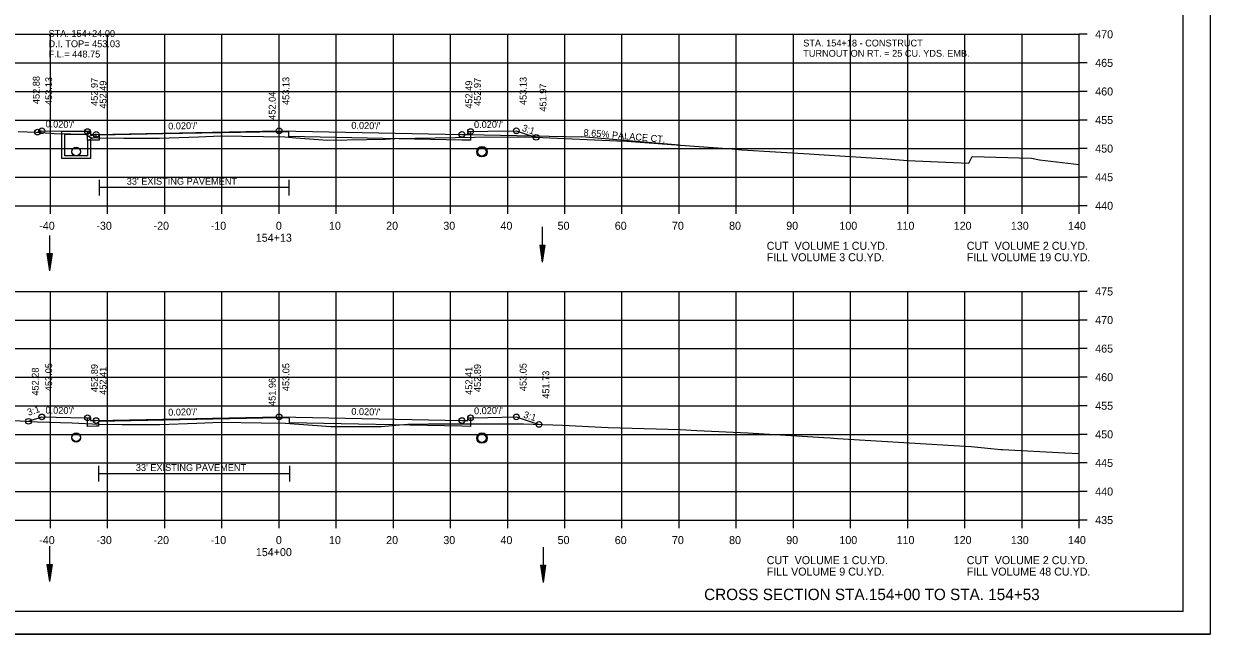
# Model space of a CAD drawing. Extents: x 1538688 to 1540766, y 656250 to 671912.
# Drawn here: x 1538813.5 to 1539021.1, y 665511.4 to 665618.3 of the extents above; entities that cross this region are included whole.
import ezdxf

# ---------------------------------------------------------------- set-up
doc = ezdxf.new("R2010")
doc.units = 0
for name, color, linetype in [('15', 7, 'Continuous'), ('16', 7, 'Continuous'), ('18', 7, 'Continuous'), ('20', 7, 'Continuous'), ('22', 7, 'Continuous'), ('26', 7, 'Continuous'), ('39', 7, 'Continuous'), ('40', 7, 'Continuous'), ('41', 7, 'Continuous'), ('42', 7, 'Continuous'), ('7', 7, 'Continuous'), ('Borings', 7, 'Continuous'), ('Horizontal Alignment', 7, 'Continuous'), ('RipRap', 7, 'Continuous'), ('Wall Heights', 7, 'Continuous')]:
    doc.layers.add(name, color=color, linetype=linetype)

msp = doc.modelspace()

# ---------------------------------------------------------------- linework, layer by layer
at = {"layer": '15'}
for p, q in [((1538817.56, 665578.04), (1538818.01, 665575.04)), ((1538817.56, 665578.04), (1538818.46, 665578.04)), ((1538817.64, 665578.04), (1538818.01, 665575.54)), ((1538817.71, 665578.04), (1538818.01, 665576.06)), ((1538817.79, 665578.04), (1538818.01, 665576.56)), ((1538817.87, 665578.04), (1538818.01, 665577.07)), ((1538817.94, 665578.04), (1538818.01, 665577.57)), ((1538818.46, 665578.04), (1538818.01, 665575.04)), ((1538818.16, 665578.04), (1538818.01, 665577.07)), ((1538818.31, 665578.04), (1538818.01, 665576.06)), ((1538818.39, 665578.04), (1538818.01, 665575.54)), ((1538818.23, 665578.04), (1538818.01, 665576.56)), ((1538818.08, 665578.04), (1538818.01, 665577.57)), ((1538903.79, 665579.51), (1538904.24, 665576.51)), ((1538903.79, 665579.51), (1538904.69, 665579.51)), ((1538903.86, 665579.51), (1538904.24, 665577.01)), ((1538903.94, 665579.51), (1538904.24, 665577.53)), ((1538904.02, 665579.51), (1538904.24, 665578.03)), ((1538904.09, 665579.51), (1538904.24, 665578.54)), ((1538904.17, 665579.51), (1538904.24, 665579.04)), ((1538904.69, 665579.51), (1538904.24, 665576.51)), ((1538904.39, 665579.51), (1538904.24, 665578.54)), ((1538904.54, 665579.51), (1538904.24, 665577.53)), ((1538904.61, 665579.51), (1538904.24, 665577.01)), ((1538904.46, 665579.51), (1538904.24, 665578.03)), ((1538904.31, 665579.51), (1538904.24, 665579.04)), ((1538817.56, 665523.65), (1538818.01, 665520.65)), ((1538817.56, 665523.65), (1538818.46, 665523.65)), ((1538817.64, 665523.65), (1538818.01, 665521.15)), ((1538817.71, 665523.65), (1538818.01, 665521.67)), ((1538817.79, 665523.65), (1538818.01, 665522.16)), ((1538817.87, 665523.65), (1538818.01, 665522.67)), ((1538817.94, 665523.65), (1538818.01, 665523.17)), ((1538818.46, 665523.65), (1538818.01, 665520.65)), ((1538818.16, 665523.65), (1538818.01, 665522.67)), ((1538818.31, 665523.65), (1538818.01, 665521.67)), ((1538818.39, 665523.65), (1538818.01, 665521.15)), ((1538818.23, 665523.65), (1538818.01, 665522.16)), ((1538818.08, 665523.65), (1538818.01, 665523.17)), ((1538903.92, 665523.5), (1538904.37, 665520.5)), ((1538903.92, 665523.5), (1538904.82, 665523.5)), ((1538904, 665523.5), (1538904.37, 665521)), ((1538904.07, 665523.5), (1538904.37, 665521.52)), ((1538904.15, 665523.5), (1538904.37, 665522.02)), ((1538904.23, 665523.5), (1538904.37, 665522.52)), ((1538904.3, 665523.5), (1538904.37, 665523.03)), ((1538904.82, 665523.5), (1538904.37, 665520.5)), ((1538904.52, 665523.5), (1538904.37, 665522.52)), ((1538904.67, 665523.5), (1538904.37, 665521.52)), ((1538904.75, 665523.5), (1538904.37, 665521)), ((1538904.6, 665523.5), (1538904.37, 665522.02)), ((1538904.44, 665523.5), (1538904.37, 665523.03))]:
    msp.add_line(p, q, dxfattribs=at)
at = {"layer": '16'}
for p in [(1538891.18, 665598.88), (1538928.17, 665597.01)]:
    msp.add_line(p, (1538911.17, 665598.48), dxfattribs=at)
at = {"layer": '18'}
for points in [[(1538812.51, 665599.4), (1538815.69, 665599.31), (1538818.82, 665599.07), (1538821.76, 665599.01), (1538824.37, 665598.95), (1538825.01, 665598.44), (1538825.07, 665598.39), (1538825.24, 665598.38), (1538826.59, 665598.27), (1538831.03, 665598.25), (1538837.25, 665598.23), (1538844.07, 665598.47), (1538847.97, 665598.62), (1538851.71, 665598.56), (1538859.17, 665598.44), (1538861.12, 665598.29), (1538866.67, 665597.87), (1538873.45, 665598.03), (1538876.66, 665598.05), (1538878.42, 665598.16), (1538889.06, 665598.37), (1538892.38, 665598.39), (1538901.31, 665598.44), (1538904.28, 665598.35), (1538917.29, 665597.77), (1538919.02, 665597.71), (1538928.42, 665596.99), (1538937.38, 665596.34), (1538939.14, 665596.22), (1538950.91, 665595.48), (1538953.54, 665595.29), (1538964.56, 665594.6), (1538968.14, 665594.35), (1538978.89, 665593.88), (1538979.47, 665595.05), (1538989.81, 665594.75), (1538991.24, 665594.44), (1538998.18, 665593.65)], [(1538811.87, 665548.81), (1538815.9, 665548.61), (1538821.98, 665548.43), (1538826.7, 665548.18), (1538830.74, 665548.16), (1538837.29, 665548.14), (1538843.79, 665548.38), (1538848.02, 665548.53), (1538855.07, 665548.42), (1538859.22, 665548.36), (1538866.45, 665547.82), (1538867.21, 665547.78), (1538868.76, 665547.78), (1538876.05, 665547.81), (1538879.26, 665548.09), (1538880.72, 665548.22), (1538884.33, 665548.24), (1538900.92, 665548.24), (1538907.77, 665548), (1538915.74, 665547.61), (1538928.37, 665547.24), (1538931.29, 665547.11), (1538940.21, 665546.66), (1538953.5, 665545.85), (1538954.63, 665545.78), (1538955.87, 665545.7), (1538976.25, 665544.44), (1538979.29, 665544.31), (1538984.49, 665543.78), (1538984.73, 665543.77), (1538995.69, 665543.19), (1538998.18, 665543.05)]]:
    msp.add_lwpolyline(points, dxfattribs=at)
at = {"layer": '20'}
for points in [[(1538815.92, 665599.29), (1538816.67, 665599.54), (1538821.67, 665599.44), (1538824.67, 665599.38), (1538825.17, 665599.38), (1538825.18, 665598.88), (1538826.18, 665598.9), (1538858.18, 665599.54), (1538890.18, 665598.9), (1538891.18, 665598.88), (1538891.19, 665599.38), (1538891.69, 665599.38), (1538894.69, 665599.44), (1538899.69, 665599.54), (1538903.16, 665598.38)], [(1538814.33, 665548.69), (1538816.67, 665549.47), (1538821.67, 665549.37), (1538824.67, 665549.31), (1538825.17, 665549.31), (1538825.18, 665548.81), (1538826.18, 665548.83), (1538858.18, 665549.47), (1538890.18, 665548.83), (1538891.18, 665548.81), (1538891.19, 665549.31), (1538891.69, 665549.31), (1538894.69, 665549.37), (1538899.69, 665549.47), (1538903.66, 665548.14)]]:
    msp.add_lwpolyline(points, dxfattribs=at)
at = {"layer": '22'}
for p, q in [((1538718.18, 665616.41), (1538998.18, 665616.41)), ((1538818.18, 665586.41), (1538818.18, 665616.41)), ((1538828.18, 665586.41), (1538828.18, 665616.41)), ((1538838.18, 665586.41), (1538838.18, 665616.41)), ((1538848.18, 665586.41), (1538848.18, 665616.41)), ((1538858.18, 665586.41), (1538858.18, 665616.41)), ((1538868.18, 665586.41), (1538868.18, 665616.41)), ((1538878.18, 665586.41), (1538878.18, 665616.41)), ((1538888.18, 665586.41), (1538888.18, 665616.41)), ((1538898.18, 665586.41), (1538898.18, 665616.41)), ((1538908.18, 665586.41), (1538908.18, 665616.41)), ((1538918.18, 665586.41), (1538918.18, 665616.41)), ((1538928.18, 665586.41), (1538928.18, 665616.41)), ((1538938.18, 665586.41), (1538938.18, 665616.41)), ((1538948.18, 665586.41), (1538948.18, 665616.41)), ((1538958.18, 665586.41), (1538958.18, 665616.41)), ((1538968.18, 665586.41), (1538968.18, 665616.41)), ((1538978.18, 665586.41), (1538978.18, 665616.41)), ((1538988.18, 665586.41), (1538988.18, 665616.41)), ((1538998.18, 665586.41), (1538998.18, 665616.41)), ((1538718.18, 665611.41), (1538998.18, 665611.41)), ((1538718.18, 665606.41), (1538998.18, 665606.41)), ((1538718.18, 665601.41), (1538998.18, 665601.41)), ((1538718.18, 665596.41), (1538998.18, 665596.41)), ((1538718.18, 665591.41), (1538998.18, 665591.41)), ((1538718.18, 665586.41), (1538998.18, 665586.41)), ((1538718.18, 665571.41), (1538998.18, 665571.41)), ((1538818.18, 665531.41), (1538818.18, 665571.41)), ((1538828.18, 665531.41), (1538828.18, 665571.41)), ((1538838.18, 665531.41), (1538838.18, 665571.41)), ((1538848.18, 665531.41), (1538848.18, 665571.41)), ((1538858.18, 665531.41), (1538858.18, 665571.41)), ((1538868.18, 665531.41), (1538868.18, 665571.41)), ((1538878.18, 665531.41), (1538878.18, 665571.41)), ((1538888.18, 665531.41), (1538888.18, 665571.41)), ((1538898.18, 665531.41), (1538898.18, 665571.41)), ((1538908.18, 665531.41), (1538908.18, 665571.41)), ((1538918.18, 665531.41), (1538918.18, 665571.41)), ((1538928.18, 665531.41), (1538928.18, 665571.41)), ((1538938.18, 665531.41), (1538938.18, 665571.41)), ((1538948.18, 665531.41), (1538948.18, 665571.41)), ((1538958.18, 665531.41), (1538958.18, 665571.41)), ((1538968.18, 665531.41), (1538968.18, 665571.41)), ((1538978.18, 665531.41), (1538978.18, 665571.41)), ((1538988.18, 665531.41), (1538988.18, 665571.41)), ((1538998.18, 665531.41), (1538998.18, 665571.41)), ((1538718.18, 665566.41), (1538998.18, 665566.41)), ((1538718.18, 665561.41), (1538998.18, 665561.41)), ((1538718.18, 665556.41), (1538998.18, 665556.41)), ((1538718.18, 665551.41), (1538998.18, 665551.41)), ((1538718.18, 665546.41), (1538998.18, 665546.41)), ((1538718.18, 665541.41), (1538998.18, 665541.41)), ((1538718.18, 665536.41), (1538998.18, 665536.41)), ((1538718.18, 665531.41), (1538998.18, 665531.41))]:
    msp.add_line(p, q, dxfattribs=at)
at = {"layer": '26'}
msp.add_line((1538687.78, 665511.44), (1539021.11, 665511.44), dxfattribs=at)
msp.add_lwpolyline([(1538687.77, 665724.77), (1539021.11, 665724.77), (1539021.11, 665511.43), (1538687.77, 665511.43)], close=True, dxfattribs=at)
for centre, radius in [((1538815.92, 665599.29), 0.5), ((1538816.67, 665599.54), 0.5), ((1538824.67, 665599.38), 0.5), ((1538826.18, 665598.9), 0.5), ((1538858.18, 665599.54), 0.5), ((1538890.18, 665598.9), 0.5), ((1538891.69, 665599.38), 0.5), ((1538899.69, 665599.54), 0.5), ((1538903.16, 665598.38), 0.5), ((1538893.68, 665595.86), 0.917), ((1538814.33, 665548.69), 0.5), ((1538816.67, 665549.47), 0.5), ((1538824.67, 665549.31), 0.5), ((1538826.18, 665548.83), 0.5), ((1538858.18, 665549.47), 0.5), ((1538890.18, 665548.83), 0.5), ((1538891.69, 665549.31), 0.5), ((1538899.69, 665549.47), 0.5), ((1538903.66, 665548.14), 0.5), ((1538893.68, 665545.76), 0.917)]:
    msp.add_circle(centre, radius, dxfattribs=at)
at = {"layer": '39'}
for p, q in [((1538820.18, 665599.44), (1538824.93, 665599.44)), ((1538820.18, 665597.94), (1538820.18, 665599.44)), ((1538820.68, 665597.94), (1538820.68, 665598.94)), ((1538820.68, 665598.94), (1538824.68, 665598.94)), ((1538825.01, 665599.28), (1538824.68, 665598.94)), ((1538826.18, 665598.96), (1538824.68, 665598.44)), ((1538824.68, 665597.94), (1538824.68, 665598.44)), ((1538825.01, 665599.28), (1538824.93, 665599.44)), ((1538826.18, 665598.43), (1538825.18, 665598.09)), ((1538825.18, 665597.94), (1538825.18, 665598.09)), ((1538904.24, 665582.7), (1538904.24, 665576.51)), ((1538818.01, 665581.23), (1538818.01, 665575.04)), ((1538818.01, 665526.84), (1538818.01, 665520.65)), ((1538904.37, 665526.69), (1538904.37, 665520.5))]:
    msp.add_line(p, q, dxfattribs=at)
for points in [[(1538826.18, 665598.43), (1538826.18, 665598.96)], [(1538825.18, 665597.94), (1538825.18, 665594.66), (1538822.68, 665594.66), (1538820.18, 665594.66), (1538820.18, 665597.94)], [(1538824.68, 665597.94), (1538824.68, 665595.16), (1538822.68, 665595.16), (1538820.68, 665595.16), (1538820.68, 665597.94)]]:
    msp.add_lwpolyline(points, dxfattribs=at)
for centre in [(1538822.68, 665595.91), (1538822.68, 665595.87), (1538893.68, 665595.86), (1538822.68, 665545.91), (1538822.68, 665545.8), (1538893.68, 665545.76)]:
    msp.add_circle(centre, 0.75, dxfattribs=at)
at = {"layer": '7'}
for p, q in [((1538826.71, 665590.96), (1538826.71, 665588.21)), ((1538859.9, 665590.96), (1538859.9, 665588.21)), ((1538859.9, 665589.59), (1538826.71, 665589.59)), ((1538826.58, 665540.89), (1538826.58, 665538.14)), ((1538860.02, 665540.89), (1538860.02, 665538.14)), ((1538860.02, 665539.52), (1538826.58, 665539.52))]:
    msp.add_line(p, q, dxfattribs=at)
at = {"layer": 'Borings'}
for p, q in [((1538998.18, 665586.41), (1538998.18, 665616.41)), ((1538999.58, 665616.41), (1538998.18, 665616.41)), ((1538999.58, 665611.41), (1538998.18, 665611.41)), ((1538999.58, 665606.41), (1538998.18, 665606.41)), ((1538999.58, 665601.41), (1538998.18, 665601.41)), ((1538999.58, 665596.41), (1538998.18, 665596.41)), ((1538999.58, 665591.41), (1538998.18, 665591.41)), ((1538718.18, 665586.41), (1538998.18, 665586.41)), ((1538818.18, 665585.01), (1538818.18, 665586.41)), ((1538828.18, 665585.01), (1538828.18, 665586.41)), ((1538838.18, 665585.01), (1538838.18, 665586.41)), ((1538848.18, 665585.01), (1538848.18, 665586.41)), ((1538858.18, 665585.01), (1538858.18, 665586.41)), ((1538868.18, 665585.01), (1538868.18, 665586.41)), ((1538878.18, 665585.01), (1538878.18, 665586.41)), ((1538888.18, 665585.01), (1538888.18, 665586.41)), ((1538898.18, 665585.01), (1538898.18, 665586.41)), ((1538908.18, 665585.01), (1538908.18, 665586.41)), ((1538918.18, 665585.01), (1538918.18, 665586.41)), ((1538928.18, 665585.01), (1538928.18, 665586.41)), ((1538938.18, 665585.01), (1538938.18, 665586.41)), ((1538948.18, 665585.01), (1538948.18, 665586.41)), ((1538958.18, 665585.01), (1538958.18, 665586.41)), ((1538968.18, 665585.01), (1538968.18, 665586.41)), ((1538978.18, 665585.01), (1538978.18, 665586.41)), ((1538988.18, 665585.01), (1538988.18, 665586.41)), ((1538998.18, 665585.01), (1538998.18, 665586.41)), ((1538999.58, 665586.41), (1538998.18, 665586.41)), ((1538998.18, 665531.41), (1538998.18, 665571.41)), ((1538999.58, 665571.41), (1538998.18, 665571.41)), ((1538999.58, 665566.41), (1538998.18, 665566.41)), ((1538999.58, 665561.41), (1538998.18, 665561.41)), ((1538999.58, 665556.41), (1538998.18, 665556.41)), ((1538999.58, 665551.41), (1538998.18, 665551.41)), ((1538999.58, 665546.41), (1538998.18, 665546.41)), ((1538999.58, 665541.41), (1538998.18, 665541.41)), ((1538999.58, 665536.41), (1538998.18, 665536.41)), ((1538718.18, 665531.41), (1538998.18, 665531.41)), ((1538818.18, 665530.01), (1538818.18, 665531.41)), ((1538828.18, 665530.01), (1538828.18, 665531.41)), ((1538838.18, 665530.01), (1538838.18, 665531.41)), ((1538848.18, 665530.01), (1538848.18, 665531.41)), ((1538858.18, 665530.01), (1538858.18, 665531.41)), ((1538868.18, 665530.01), (1538868.18, 665531.41)), ((1538878.18, 665530.01), (1538878.18, 665531.41)), ((1538888.18, 665530.01), (1538888.18, 665531.41)), ((1538898.18, 665530.01), (1538898.18, 665531.41)), ((1538908.18, 665530.01), (1538908.18, 665531.41)), ((1538918.18, 665530.01), (1538918.18, 665531.41)), ((1538928.18, 665530.01), (1538928.18, 665531.41)), ((1538938.18, 665530.01), (1538938.18, 665531.41)), ((1538948.18, 665530.01), (1538948.18, 665531.41)), ((1538958.18, 665530.01), (1538958.18, 665531.41)), ((1538968.18, 665530.01), (1538968.18, 665531.41)), ((1538978.18, 665530.01), (1538978.18, 665531.41)), ((1538988.18, 665530.01), (1538988.18, 665531.41)), ((1538998.18, 665530.01), (1538998.18, 665531.41)), ((1538999.58, 665531.41), (1538998.18, 665531.41))]:
    msp.add_line(p, q, dxfattribs=at)
at = {"layer": 'RipRap'}
for q in [(1539016.36, 665720.87), (1538700.18, 665515.41)]:
    msp.add_line((1539016.36, 665515.41), q, dxfattribs=at)
at = {"layer": 'Wall Heights'}
for points in [[(1538891.69, 665599.38), (1538891.69, 665597.88), (1538890.18, 665597.9), (1538859.91, 665598.51), (1538859.91, 665599.34), (1538858.18, 665599.37), (1538837.91, 665598.97), (1538826.71, 665598.74), (1538826.71, 665597.91), (1538826.18, 665597.9), (1538824.67, 665597.88), (1538824.67, 665599.38)], [(1538891.69, 665549.31), (1538891.69, 665547.81), (1538890.18, 665547.83), (1538860.03, 665548.44), (1538860.03, 665549.27), (1538858.18, 665549.3), (1538838.03, 665548.9), (1538826.58, 665548.67), (1538826.58, 665547.84), (1538826.18, 665547.83), (1538824.67, 665547.81), (1538824.67, 665549.31)]]:
    msp.add_lwpolyline(points, dxfattribs=at)

# ---------------------------------------------------------------- texts
at = {"layer": '15'}
msp.add_text('CROSS SECTION STA.154+00 TO STA. 154+53', height=2, dxfattribs=at).set_placement((1538932.55, 665517.41))
at = {"layer": '16'}
msp.add_text('8.65% PALACE CT.', height=1.2, rotation=355.0557, dxfattribs=at).set_placement((1538911.41, 665598.66))
at = {"layer": '40'}
for s, p in [('STA. 154+24.00', (1538817.84, 665615.95)), ('D.I. TOP= 453.03', (1538817.84, 665614.15)), ('F.L.= 448.75', (1538817.84, 665612.35))]:
    msp.add_text(s, height=1.2, dxfattribs=at).set_placement(p)
at = {"layer": '41'}
for s, p in [('452.88', (1538816.3, 665604.2)), ('453.13', (1538818.47, 665604.04)), ('452.97', (1538826.47, 665603.88)), ('453.13', (1538859.98, 665604.04)), ('452.97', (1538893.49, 665603.88)), ('453.13', (1538901.49, 665604.04)), ('452.49', (1538827.98, 665603.4)), ('452.49', (1538891.98, 665603.4)), ('451.97', (1538904.96, 665602.88)), ('452.04', (1538857.58, 665601.45)), ('452.28', (1538816.13, 665553.19)), ('453.05', (1538818.47, 665553.97)), ('452.89', (1538826.47, 665553.81)), ('452.41', (1538827.98, 665553.33)), ('453.05', (1538859.98, 665553.97)), ('452.41', (1538891.98, 665553.33)), ('452.89', (1538893.49, 665553.81)), ('453.05', (1538901.49, 665553.97)), ('451.73', (1538905.46, 665552.64)), ('451.96', (1538857.58, 665551.38))]:
    msp.add_text(s, height=1.2, rotation=90, dxfattribs=at).set_placement(p)
at = {"layer": '42'}
for s, rotation, p in [("0.020'/'", 358.8542, (1538817.3, 665600.13)), ("0.020'/'", 1.1458, (1538838.79, 665599.75)), ("0.020'/'", 358.8542, (1538870.81, 665599.89)), ("0.020'/'", 1.1458, (1538892.3, 665599.99)), ('3:1', 341.5651, (1538900.58, 665599.54)), ('3:1', 18.4349, (1538814.34, 665549.65)), ("0.020'/'", 358.8542, (1538817.3, 665550.06)), ("0.020'/'", 1.1458, (1538838.79, 665549.68)), ("0.020'/'", 358.8542, (1538870.81, 665549.82)), ("0.020'/'", 1.1458, (1538892.3, 665549.92)), ('3:1', 341.5651, (1538900.83, 665549.38))]:
    msp.add_text(s, height=1.2, rotation=rotation, dxfattribs=at).set_placement(p)
at = {"layer": '7'}
for s, p in [('STA. 154+18 - CONSTRUCT', (1538949.89, 665614.28)), ('TURNOUT ON RT. = 25 CU. YDS. EMB.', (1538949.89, 665612.48)), ("33' EXISTING PAVEMENT", (1538831.53, 665590.09)), ("33' EXISTING PAVEMENT", (1538833.12, 665540.01))]:
    msp.add_text(s, height=1.2, dxfattribs=at).set_placement(p)
at = {"layer": 'Horizontal Alignment'}
for s, p in [('470', (1539000.98, 665615.71)), ('465', (1539000.98, 665610.71)), ('460', (1539000.98, 665605.71)), ('455', (1539000.98, 665600.71)), ('450', (1539000.98, 665595.71)), ('445', (1539000.98, 665590.71)), ('440', (1539000.98, 665585.71)), ('-40', (1538816.22, 665582.21)), ('-30', (1538826.22, 665582.21)), ('-20', (1538836.22, 665582.21)), ('-10', (1538846.22, 665582.21)), ('0', (1538857.62, 665582.21)), ('10', (1538866.92, 665582.21)), ('20', (1538876.92, 665582.21)), ('30', (1538886.92, 665582.21)), ('40', (1538896.92, 665582.21)), ('50', (1538906.92, 665582.21)), ('60', (1538916.92, 665582.21)), ('70', (1538926.92, 665582.21)), ('80', (1538936.92, 665582.21)), ('90', (1538946.92, 665582.21)), ('100', (1538956.22, 665582.21)), ('110', (1538966.22, 665582.21)), ('120', (1538976.22, 665582.21)), ('130', (1538986.22, 665582.21)), ('140', (1538996.22, 665582.21)), ('154+13', (1538854.11, 665580.11)), ('CUT  VOLUME 1 CU.YD.', (1538943.5, 665578.7)), ('CUT  VOLUME 2 CU.YD.', (1538978.5, 665578.7)), ('FILL VOLUME 3 CU.YD.', (1538943.5, 665576.7)), ('FILL VOLUME 19 CU.YD.', (1538978.5, 665576.7)), ('475', (1539000.98, 665570.71)), ('470', (1539000.98, 665565.71)), ('465', (1539000.98, 665560.71)), ('460', (1539000.98, 665555.71)), ('455', (1539000.98, 665550.71)), ('450', (1539000.98, 665545.71)), ('445', (1539000.98, 665540.71)), ('440', (1539000.98, 665535.71)), ('435', (1539000.98, 665530.71)), ('-40', (1538816.22, 665527.21)), ('-30', (1538826.22, 665527.21)), ('-20', (1538836.22, 665527.21)), ('-10', (1538846.22, 665527.21)), ('0', (1538857.62, 665527.21)), ('10', (1538866.92, 665527.21)), ('20', (1538876.92, 665527.21)), ('30', (1538886.92, 665527.21)), ('40', (1538896.92, 665527.21)), ('50', (1538906.92, 665527.21)), ('60', (1538916.92, 665527.21)), ('70', (1538926.92, 665527.21)), ('80', (1538936.92, 665527.21)), ('90', (1538946.92, 665527.21)), ('100', (1538956.22, 665527.21)), ('110', (1538966.22, 665527.21)), ('120', (1538976.22, 665527.21)), ('130', (1538986.22, 665527.21)), ('140', (1538996.22, 665527.21)), ('154+00', (1538854.12, 665525.11)), ('CUT  VOLUME 1 CU.YD.', (1538943.5, 665523.7)), ('CUT  VOLUME 2 CU.YD.', (1538978.5, 665523.7)), ('FILL VOLUME 9 CU.YD.', (1538943.5, 665521.7)), ('FILL VOLUME 48 CU.YD.', (1538978.5, 665521.7))]:
    msp.add_text(s, height=1.4, dxfattribs=at).set_placement(p)

doc.saveas('drawing.dxf')
